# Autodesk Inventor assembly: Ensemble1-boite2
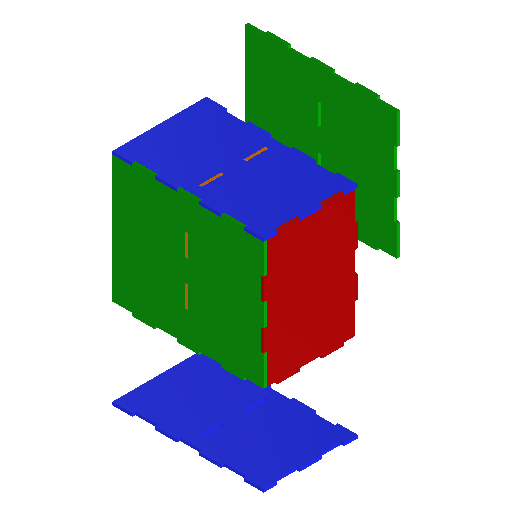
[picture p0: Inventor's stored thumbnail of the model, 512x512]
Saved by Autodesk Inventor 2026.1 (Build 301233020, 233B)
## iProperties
Created: 2023-12
Part Number: Ensemble1-boite2
Document SubType Name: Assembly
Designer: bruno
Author: bruno
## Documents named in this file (7)
- M:\STI2D\IT\Escape game\Escape-game\Boite\boite_fixe.iam
- M:\STI2D\IT\Escape game\Escape-game\Boite\boite_fixe_grand_cote.ipt
- M:\STI2D\IT\Escape game\Escape-game\Boite\boite_fixe_petit_cote.ipt
- M:\STI2D\IT\Escape game\Escape-game\Boite\boite_fixe_fond.ipt
- M:\STI2D\IT\Escape game\Escape-game\Boite\boite_fixe_milieu.ipt
- M:\STI2D\IT\Escape game\Escape-game\MotoreducteurRB35\motoeeducteur_corps.ipt
- M:\STI2D\IT\Escape game\Escape-game\Raspberry-pi-pico\Ensemble-raspberry.iam
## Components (8 placed, 6 different names)
1. boite_fixe_grand_cote:1 — Affleurement:1, Placage:1, Affleurement:2, Placage:2, Placage:4, Affleurement:9, Affleurement:10
2. boite_fixe_petit_cote:1 — Affleurement:1, Placage:1, Affleurement:2, Affleurement:3, Affleurement:4, Affleurement:5, Affleurement:6, Placage:7, Angle:1
3. boite_fixe_fond:1 — Placage:2, Affleurement:3, Affleurement:4, Placage:3
4. boite_fixe_milieu:1 — Placage:3, Placage:4, Affleurement:5, Logement:1
5. motoeeducteur_corps:1 — Logement:1
6. boite_fixe_grand_cote:2 — Affleurement:6
7. boite_fixe_petit_cote:2 — Affleurement:9, Affleurement:10
8. Ensemble-raspberry:1 [sub-assembly] — Placage:7, Angle:1
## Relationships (15: Flush 8, Mate 5, Insert 1, Angle 1)
- Affleurement:1 [Flush]: boite_fixe_grand_cote:1 ↔ boite_fixe_petit_cote:1
- Placage:1 [Mate]: boite_fixe_grand_cote:1 ↔ boite_fixe_petit_cote:1
- Affleurement:2 [Flush]: boite_fixe_grand_cote:1 ↔ boite_fixe_petit_cote:1
- Placage:2 [Mate]: boite_fixe_grand_cote:1 ↔ boite_fixe_fond:1
- Affleurement:3 [Flush]: boite_fixe_petit_cote:1 ↔ boite_fixe_fond:1
- Affleurement:4 [Flush]: boite_fixe_petit_cote:1 ↔ boite_fixe_fond:1
- Placage:3 [Mate]: boite_fixe_fond:1 ↔ boite_fixe_milieu:1
- Placage:4 [Mate]: boite_fixe_grand_cote:1 ↔ boite_fixe_milieu:1
- Affleurement:5 [Flush]: boite_fixe_petit_cote:1 ↔ boite_fixe_milieu:1
- Logement:1 [Insert]: boite_fixe_milieu:1 ↔ motoeeducteur_corps:1
- Affleurement:6 [Flush]: boite_fixe_petit_cote:1 ↔ boite_fixe_grand_cote:2
- Affleurement:9 [Flush]: boite_fixe_grand_cote:1 ↔ boite_fixe_petit_cote:2
- Affleurement:10 [Flush]: boite_fixe_grand_cote:1 ↔ boite_fixe_petit_cote:2
- Placage:7 [Mate]: boite_fixe_petit_cote:1 ↔ Ensemble-raspberry:1
- Angle:1: boite_fixe_petit_cote:1 ↔ Ensemble-raspberry:1
